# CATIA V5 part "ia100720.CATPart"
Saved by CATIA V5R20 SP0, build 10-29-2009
Part number: IA 100720
Revision: ANY
Definition: UNKNOWN
Nomenclature: IA 100720
Source: Unknown
Bounding box of the stored display mesh (mm): x -5.35 to 5.35, y -17 to 0, z -5.35 to 5.35
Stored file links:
  C:\Users\Utente\Desktop\IO LAVORO\3D X SITO CF\CUMSA\3D files IA\IA 100720\ia100720.CATPart
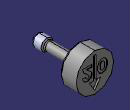
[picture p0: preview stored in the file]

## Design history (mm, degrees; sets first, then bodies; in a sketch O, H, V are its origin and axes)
Body1 "Cortar-Extruir3" (main body)
  Solid1: solid without history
